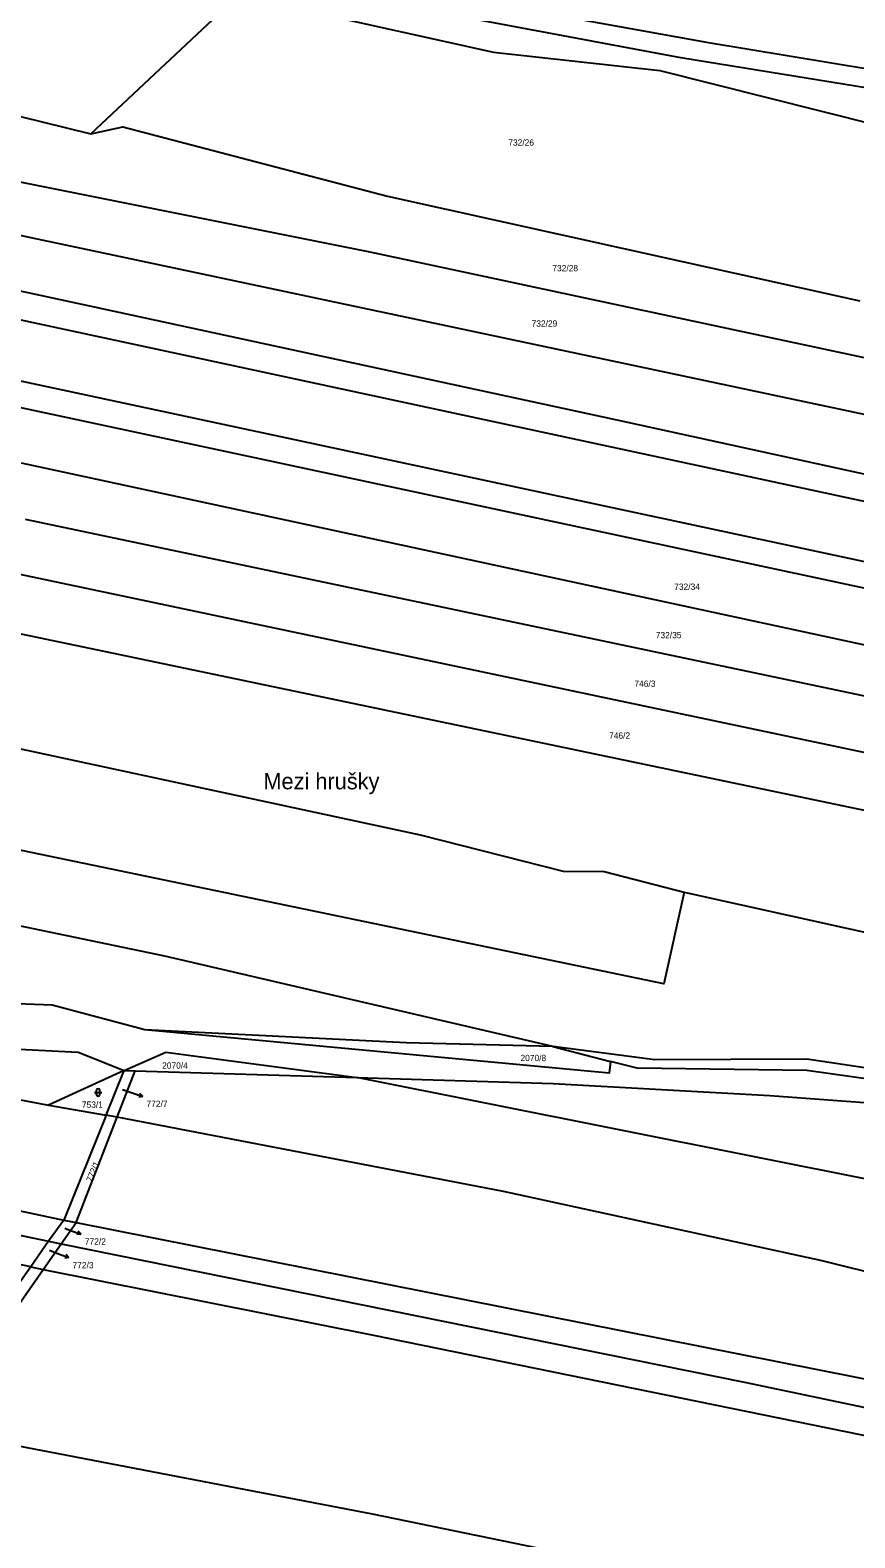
# Model space of a CAD drawing. Extents: x -755528 to -748832, y -1118122 to -1111095.
# Drawn here: x -751976.9 to -751753.8, y -1113545.6 to -1113137.8 of the extents above; entities that cross this region are included whole.
import ezdxf

# ---------------------------------------------------------------- set-up
doc = ezdxf.new("R2010")
doc.units = 0
for name, color, linetype in [('DZ_DO_PUPFL', 7, 'Continuous'), ('DZ_NAD_ZPF', 7, 'Continuous'), ('legenda barvy', 7, 'Continuous'), ('TZ_UMVŽST', 7, 'Continuous')]:
    doc.layers.add(name, color=color, linetype=linetype)

msp = doc.modelspace()

# ---------------------------------------------------------------- linework, layer by layer
at = {"layer": 'DZ_NAD_ZPF'}
for p, q in [((-751960.49, -1113165.83), (-751921.66, -1113129.33)), ((-752064.44, -1113140.18), (-751960.49, -1113165.83)), ((-752078.96, -1113408.35), (-751971.9, -1113428.55)), ((-751835.52, -1113412.7), (-751819.9, -1113416.75)), ((-751951.49, -1113419.2), (-751971.9, -1113428.55)), ((-751956.35, -1113431.25), (-751951.49, -1113419.2)), ((-751953.35, -1113431.83), (-751948.46, -1113419.29)), ((-751951.49, -1113419.2), (-751948.46, -1113419.29)), ((-751948.46, -1113419.29), (-751888.49, -1113421.13)), ((-751971.9, -1113428.55), (-751956.35, -1113431.25)), ((-751956.35, -1113431.25), (-751967.82, -1113459.66)), ((-751953.35, -1113431.83), (-751956.35, -1113431.25)), ((-751964.45, -1113460.28), (-751953.35, -1113431.83)), ((-751967.82, -1113459.66), (-751971.88, -1113465.41)), ((-751967.82, -1113459.66), (-751964.45, -1113460.28)), ((-751968.51, -1113466.1), (-751964.45, -1113460.28)), ((-751971.88, -1113465.41), (-751976.73, -1113472.29)), ((-751973.41, -1113473.07), (-751968.51, -1113466.1)), ((-751971.88, -1113465.41), (-751968.51, -1113466.1)), ((-751976.73, -1113472.29), (-751973.41, -1113473.07)), ((-752003.56, -1113516.34), (-751973.41, -1113473.07))]:
    msp.add_line(p, q, dxfattribs=at)
for points in [[(-751708.32, -1113156.87), (-751725.93, -1113157.43), (-751800.89, -1113145.26), (-751939.71, -1113119.21), (-751938.88, -1113114.95), (-751793.94, -1113141.05), (-751726.91, -1113152.19), (-751704.15, -1113151.67)], [(-751921.66, -1113129.33), (-751902.91, -1113132.45), (-751851.6, -1113143.79), (-751806.56, -1113148.68), (-751748.14, -1113163.43), (-751744.07, -1113163.17)], [(-752332.06, -1113131.3), (-752279.95, -1113144.58), (-752181.51, -1113164.69), (-751818.19, -1113243.24), (-751594.34, -1113292.21)], [(-751598.41, -1113299.35), (-751698.49, -1113276.69), (-752175.56, -1113174.09), (-752287.24, -1113151.08), (-752337.16, -1113139.71)], [(-752347.64, -1113153.5), (-752121.14, -1113202.33), (-751683.44, -1113296.03), (-751608.37, -1113312.94)], [(-752069.39, -1113156.2), (-751984.66, -1113177.88), (-751885.06, -1113197.75), (-751575.53, -1113263.93)], [(-751960.49, -1113165.83), (-751951.81, -1113163.96), (-751880.23, -1113182.72), (-751752.47, -1113211)], [(-752074.11, -1113171.47), (-751994.64, -1113190.1), (-751634.52, -1113266.49), (-751584.97, -1113277.72)], [(-752417.45, -1113237.88), (-752392.74, -1113246.44), (-752150.86, -1113297.83), (-751986.29, -1113330.78), (-751871.37, -1113355.44), (-751832.74, -1113365.29), (-751821.68, -1113365.37), (-751799.99, -1113370.97)], [(-751615.55, -1113319.24), (-751689.82, -1113301.95), (-751979.76, -1113239.86)], [(-751979.36, -1113254.86), (-751688.12, -1113317.69), (-751624.48, -1113332.34)], [(-751799.99, -1113370.97), (-751805.49, -1113395.76), (-752133.52, -1113327.68), (-752167.57, -1113319.62), (-752409.79, -1113267.64), (-752433.17, -1113259.4)], [(-751978.19, -1113270.1), (-751691.7, -1113330.42), (-751661.25, -1113337.39), (-751631.41, -1113345.86)], [(-751835.52, -1113412.7), (-751940.49, -1113388.32), (-752118.17, -1113351.34), (-752237.69, -1113324.95), (-752412.38, -1113289.63), (-752448.05, -1113279.77)], [(-751640.23, -1113359.95), (-751675.77, -1113349.15), (-751981.27, -1113284.67)], [(-751984.5, -1113299.98), (-751725.44, -1113354.16), (-751649.76, -1113373.86)], [(-752489.01, -1113350.86), (-752377.86, -1113371.15), (-752340.48, -1113378.56), (-752228.18, -1113405.52), (-752167.85, -1113417.02), (-751967.82, -1113459.66)], [(-752492.13, -1113356.72), (-752479.11, -1113360.16), (-752343.18, -1113385.36), (-752218.94, -1113414.91), (-752154.6, -1113427.43), (-751971.88, -1113465.41)], [(-751799.99, -1113370.97), (-751740.61, -1113384.1), (-751665.12, -1113402.11)], [(-751945.86, -1113408.25), (-751970.9, -1113401.55), (-751997.3, -1113400.58)], [(-752078.96, -1113408.35), (-751963.88, -1113414.22), (-751951.49, -1113419.2)], [(-751819.9, -1113416.75), (-751820.28, -1113419.9), (-751945.86, -1113408.25)], [(-751835.52, -1113412.7), (-751875.17, -1113411.71), (-751945.86, -1113408.25)], [(-751976.73, -1113472.29), (-752209.94, -1113423.55), (-752257.24, -1113412.65)], [(-751951.49, -1113419.2), (-751940.23, -1113414.23), (-751888.49, -1113421.13)], [(-751668.27, -1113433.75), (-751696.85, -1113426.57), (-751766.85, -1113416.17), (-751807.89, -1113416.28), (-751835.52, -1113412.7)], [(-751668.27, -1113433.75), (-751668.54, -1113436.41), (-751700.79, -1113428.5), (-751766.82, -1113419.17), (-751812.74, -1113418.6), (-751819.9, -1113416.75)], [(-751888.49, -1113421.13), (-751835.39, -1113422.75), (-751776.83, -1113425.93), (-751720.85, -1113430.12), (-751691, -1113433.73), (-751657.4, -1113442)], [(-751213.33, -1113558.4), (-751247.54, -1113550.28), (-751320.07, -1113539.39), (-751531.15, -1113496.48), (-751676.09, -1113463.44), (-751888.49, -1113421.13)], [(-751229.42, -1113575.55), (-751398.88, -1113546.21), (-751493.5, -1113525.18), (-751567.32, -1113512.06), (-751701.45, -1113481.78), (-751708.7, -1113484.13), (-751762.65, -1113470.73), (-751848.84, -1113451.93), (-751953.35, -1113431.83)], [(-751964.45, -1113460.28), (-751732.15, -1113506.35), (-751657.86, -1113523.45), (-751417.9, -1113573.04), (-751243.71, -1113606.12)], [(-751968.51, -1113466.1), (-751783.72, -1113503.5), (-751585.31, -1113545.16), (-751416.42, -1113580.07), (-751246.76, -1113611.48)], [(-751976.73, -1113472.29), (-752005.53, -1113513.04), (-752014.71, -1113514.24)], [(-751973.41, -1113473.07), (-751884.02, -1113490.77), (-751378.74, -1113593.96), (-751252.72, -1113615.76)], [(-751606.05, -1113598.27), (-751724.69, -1113572), (-751884.25, -1113539.2), (-752003.56, -1113516.34)]]:
    msp.add_lwpolyline(points, dxfattribs=at)
at = {"layer": 'legenda barvy'}
for p, q in [((-751951.93, -1113424.35), (-751949.25, -1113425.25)), ((-751949.25, -1113425.25), (-751946.413, -1113426.227)), ((-751946.413, -1113426.227), (-751947.522, -1113426.374)), ((-751946.413, -1113426.227), (-751947.196, -1113425.428)), ((-751967.49, -1113461.89), (-751965.93, -1113462.45)), ((-751965.93, -1113462.45), (-751963.11, -1113463.476)), ((-751963.11, -1113463.476), (-751964.222, -1113463.604)), ((-751963.11, -1113463.476), (-751963.88, -1113462.663)), ((-751971.64, -1113467.8), (-751969.21, -1113468.75)), ((-751969.21, -1113468.75), (-751966.408, -1113469.825)), ((-751966.408, -1113469.825), (-751967.523, -1113469.934)), ((-751966.408, -1113469.825), (-751967.164, -1113468.999))]:
    msp.add_line(p, q, dxfattribs=at)
at = {"layer": 'TZ_UMVŽST'}
for p, q in [((-751959.501, -1113425.131), (-751957.499, -1113425.131)), ((-751959.001, -1113424.631), (-751959.001, -1113425.632)), ((-751957.999, -1113425.632), (-751957.999, -1113424.631))]:
    msp.add_line(p, q, dxfattribs=at)
for centre, start, end in [((-751958.5, -1113424.6309), 0, 180), ((-751958.5, -1113425.6309), 180, 359.987886)]:
    msp.add_arc(centre, 0.5, start, end, dxfattribs=at)

# ---------------------------------------------------------------- texts
at = {"layer": 'DZ_DO_PUPFL'}
for s, p in [('732/26', (-751847.567, -1113169.06)), ('732/28', (-751835.657, -1113203.04)), ('732/29', (-751841.267, -1113218.01)), ('732/34', (-751802.687, -1113289.2)), ('732/35', (-751807.677, -1113302.29)), ('746/3', (-751813.448, -1113315.43)), ('746/2', (-751820.308, -1113329.46)), ('2070/8', (-751844.277, -1113416.67)), ('2070/4', (-751941.187, -1113418.71)), ('753/1', (-751962.898, -1113429.29)), ('772/7', (-751945.41, -1113429.058)), ('772/2', (-751962.1, -1113466.298)), ('772/3', (-751965.42, -1113472.698))]:
    msp.add_text(s, height=1.7, dxfattribs=at).set_placement(p)
msp.add_text('772/1', height=1.7, rotation=68, dxfattribs=at).set_placement((-751960.207, -1113449.516))
at = {"layer": 'legenda barvy'}
msp.add_text('Mezi hrušky', height=4.399998, dxfattribs=at).set_placement((-751913.805, -1113343.15))

doc.saveas('drawing.dxf')
